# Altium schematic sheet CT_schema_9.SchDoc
size 391 x 238 mm
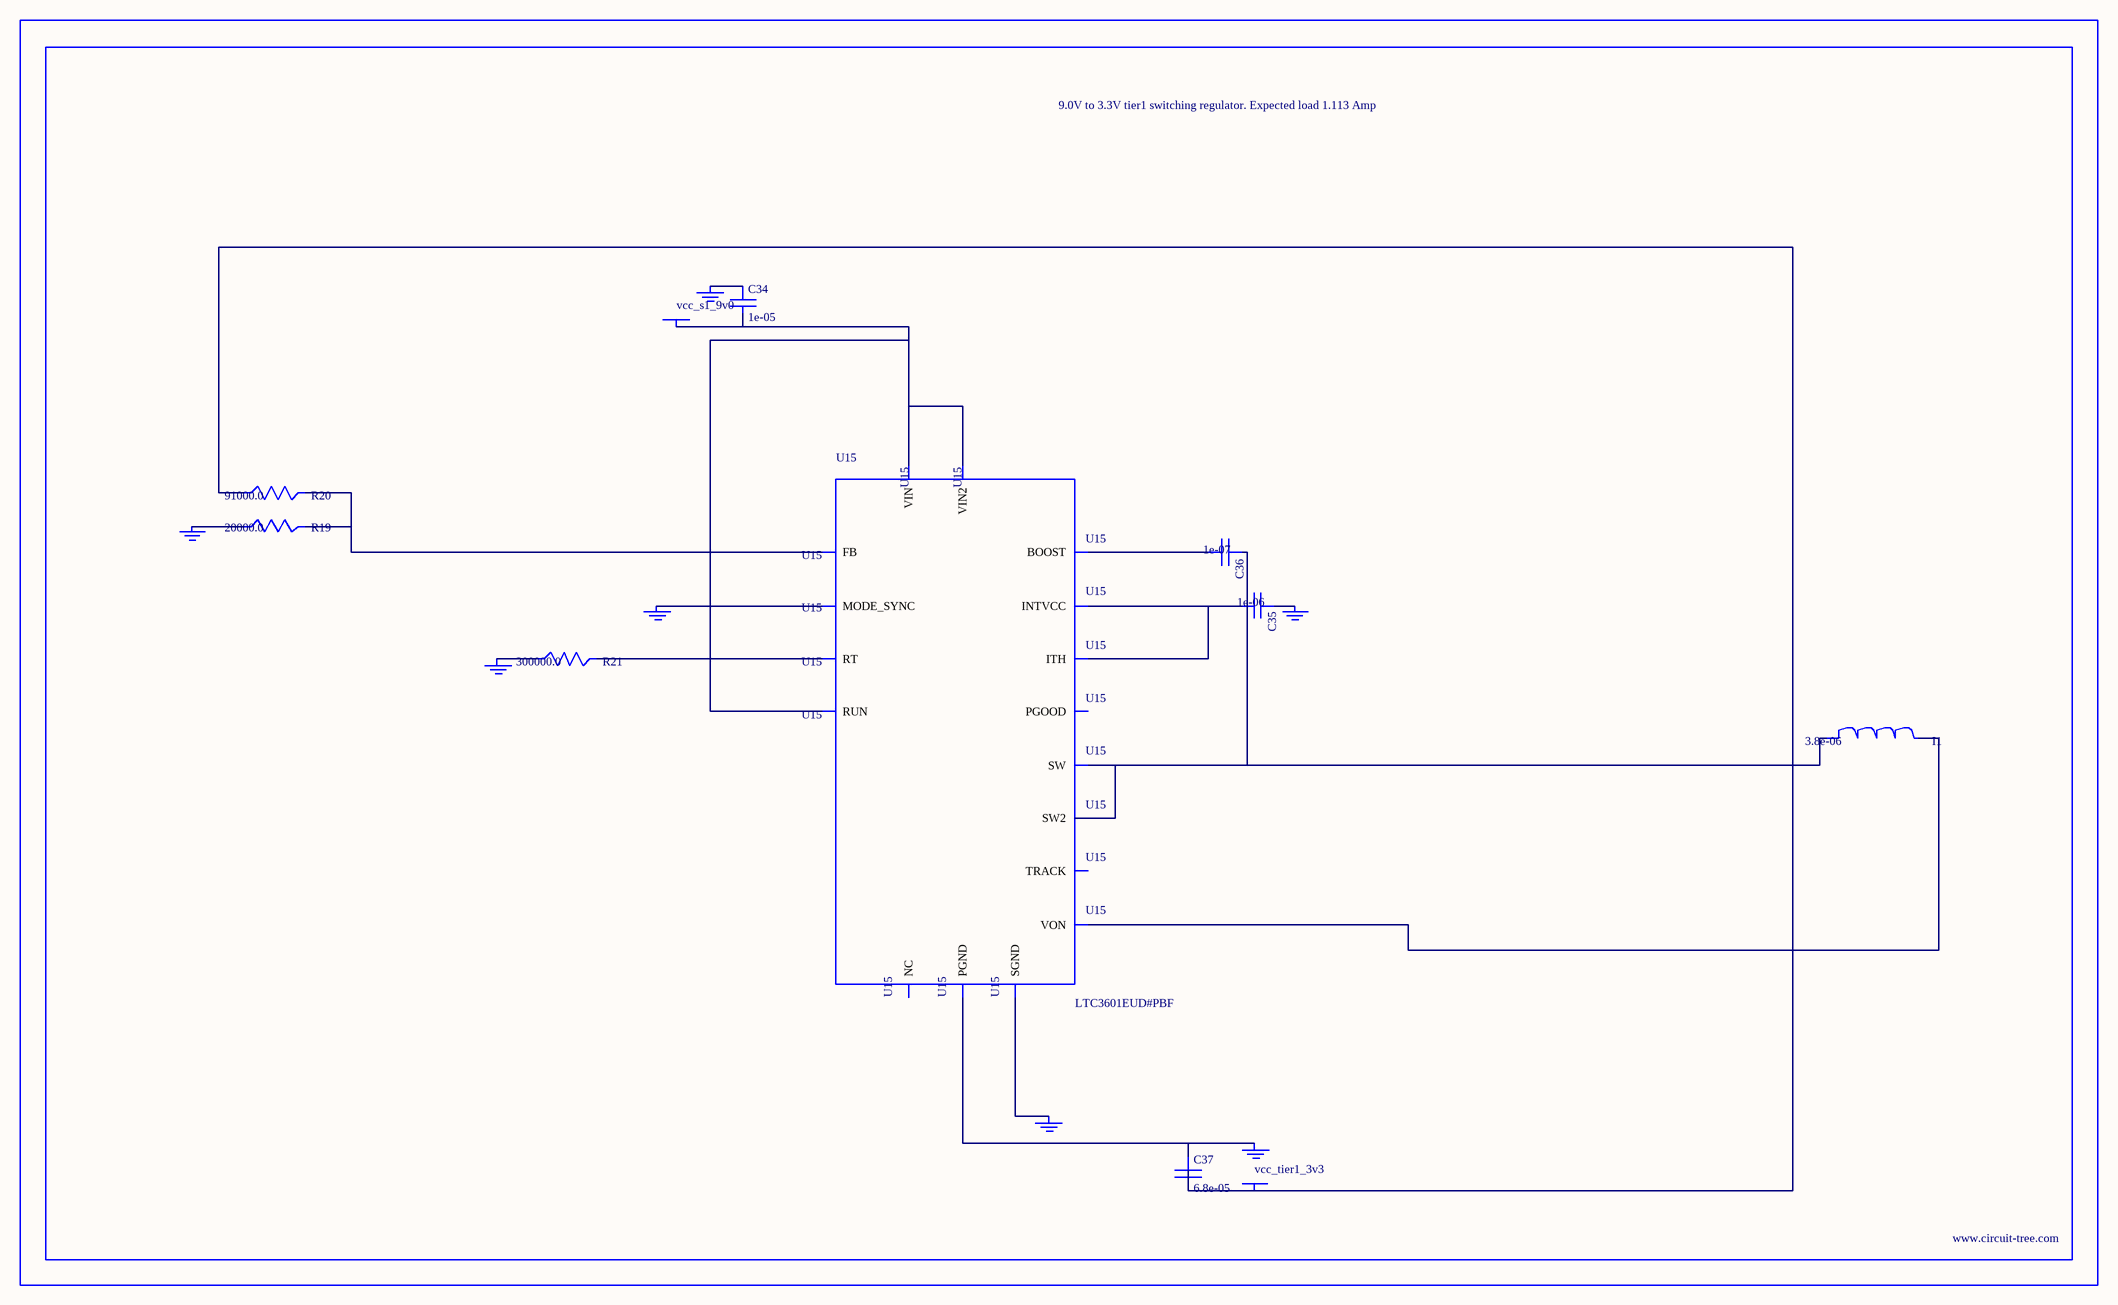
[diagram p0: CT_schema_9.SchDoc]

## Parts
BORDER8  (no value)
C34  1e-05  [C0805]
C35  1e-06  [C0603]
C36  1e-07  [C0402]
C37  6.8e-05  [2220]
GND_INSTANCE_8_0  (no value)
GND_INSTANCE_8_1  (no value)
GND_INSTANCE_8_2  (no value)
GND_INSTANCE_8_3  (no value)
GND_INSTANCE_8_4  (no value)
GND_INSTANCE_8_5  (no value)
GND_INSTANCE_8_6  (no value)
I1  3.8e-06  [DR1040]
POWER_INSTANCE_8_0  vcc_s1_9v0
POWER_INSTANCE_8_1  vcc_tier1_3v3
R19  20000.0  [R0603]
R20  91000.0  [R0603]
R21  300000.0  [R0603]
U15  LTC3601EUD#PBF  [QFN-16_EP]

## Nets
NetC34_1: C34.1 GND_INSTANCE_8_5.0(GND)
NetC34_2: C34.2 POWER_INSTANCE_8_0.0(PWR) U15.14(RUN) U15.15(VIN) U15.16(VIN2)
NetC35_1: C35.1 GND_INSTANCE_8_1.0(GND)
NetC35_2: C35.2 U15.7(INTVCC) U15.12(ITH)
NetC36_1: C36.1 I1.1 U15.3(SW) U15.4(SW2)
NetC36_2: C36.2 U15.6(BOOST)
NetC37_1: C37.1 GND_INSTANCE_8_6.0(GND) U15.17(PGND)
NetC37_2: C37.2 I1.2 POWER_INSTANCE_8_1.0(PWR) R20.1 U15.8(VON)
NetGND_INSTANCE_8_0_0: GND_INSTANCE_8_0.0(GND) U15.1(MODE_SYNC)
NetGND_INSTANCE_8_2_0: GND_INSTANCE_8_2.0(GND) U15.9(SGND)
NetGND_INSTANCE_8_3_0: GND_INSTANCE_8_3.0(GND) R21.1
NetGND_INSTANCE_8_4_0: GND_INSTANCE_8_4.0(GND) R19.1
NetR19_2: R19.2 R20.2 U15.11(FB)
NetR21_2: R21.2 U15.10(RT)

Not connected (* = marked no-connect by the designer): U15 2(PGOOD) 5(NC) 13(TRACK)

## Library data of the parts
BORDER8 = BORDER_PAGE8
C34 = C0805C106K8RACTU
C35 = C0603C105K3RACTU
C36 = C0402C104K3RACTU
C37 = C5750X5R1A686M
GND_INSTANCE_8_0-GND_INSTANCE_8_6 = GND
I1 = DR1040-3R8-R
POWER_INSTANCE_8_0 POWER_INSTANCE_8_1 = PWR
R19 = RC0603JR-0720KL
R20 = RC0603JR-0791KL
R21 = RC0603JR-07300KL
